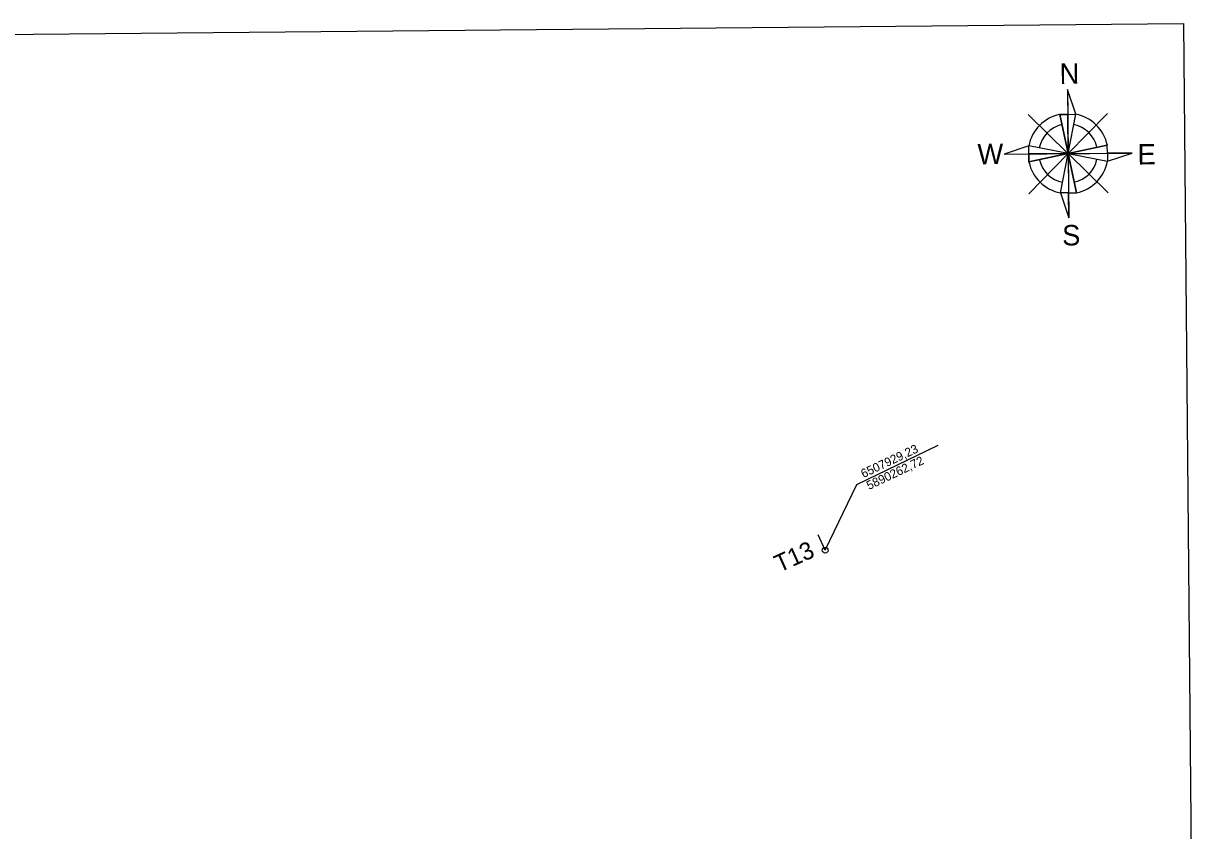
# Model space of a CAD drawing. Extents: x 6505045 to 6511721, y 5887996 to 5893535.
# Drawn here: x 6507860.2 to 6507961.4, y 5890238.6 to 5890308.1 of the extents above; entities that cross this region are included whole.
import ezdxf

# ---------------------------------------------------------------- set-up
doc = ezdxf.new("R2010")
doc.units = 0
for name, color, linetype in [('P_2 tablice LCD', 7, 'Continuous'), ('P_lokalizacja slupka', 7, 'Continuous'), ('P_opisy', 7, 'Continuous'), ('P_tabela', 7, 'Continuous'), ('P_wsporzedne', 7, 'Continuous'), ('P_znak północy', 7, 'Continuous')]:
    doc.layers.add(name, color=color, linetype=linetype)

msp = doc.modelspace()

# ---------------------------------------------------------------- linework, layer by layer
at = {"layer": 'P_2 tablice LCD'}
msp.add_line((6507929.23, 5890262.72), (6507928.62, 5890264.04), dxfattribs=at)
at = {"layer": 'P_lokalizacja slupka'}
msp.add_circle((6507929.23, 5890262.72), 0.25, dxfattribs=at)
at = {"layer": 'P_tabela'}
for p, q in [((6507759.07, 5890306.18), (6507960.06, 5890308.06)), ((6507759.07, 5890306.18), (6507960.06, 5890308.06)), ((6507759.07, 5890306.18), (6507960.06, 5890308.06)), ((6507960.06, 5890308.06), (6507961.36, 5890168.61)), ((6507960.06, 5890308.06), (6507961.36, 5890168.61)), ((6507960.06, 5890308.06), (6507961.36, 5890168.61))]:
    msp.add_line(p, q, dxfattribs=at)
at = {"layer": 'P_wsporzedne'}
for p, q in [((6507931.95, 5890268.37), (6507938.94, 5890271.76)), ((6507929.23, 5890262.72), (6507931.95, 5890268.37))]:
    msp.add_line(p, q, dxfattribs=at)
at = {"layer": 'P_znak północy'}
for p, q in [((6507950.09, 5890302.38), (6507950.19, 5890291.34)), ((6507950.09, 5890302.38), (6507950.19, 5890291.34)), ((6507950.09, 5890302.38), (6507950.19, 5890291.34)), ((6507950.09, 5890302.38), (6507950.19, 5890291.34)), ((6507950.09, 5890302.38), (6507950.19, 5890291.34)), ((6507950.09, 5890302.38), (6507950.19, 5890291.34)), ((6507950.09, 5890302.38), (6507950.19, 5890291.34)), ((6507950.09, 5890302.38), (6507950.19, 5890291.34)), ((6507950.12, 5890296.86), (6507946.69, 5890300.24)), ((6507950.12, 5890296.86), (6507946.69, 5890300.24)), ((6507950.12, 5890296.86), (6507946.69, 5890300.24)), ((6507950.12, 5890296.86), (6507946.69, 5890300.24)), ((6507950.12, 5890296.86), (6507946.69, 5890300.24)), ((6507950.12, 5890296.86), (6507946.69, 5890300.24)), ((6507950.12, 5890296.86), (6507946.69, 5890300.24)), ((6507950.12, 5890296.86), (6507946.69, 5890300.24)), ((6507949.42, 5890300.23), (6507950.11, 5890300.24)), ((6507949.42, 5890300.23), (6507950.11, 5890300.24)), ((6507949.42, 5890300.23), (6507950.11, 5890300.24)), ((6507949.42, 5890300.23), (6507950.11, 5890300.24)), ((6507949.42, 5890300.23), (6507950.11, 5890300.24)), ((6507949.42, 5890300.23), (6507950.11, 5890300.24)), ((6507949.42, 5890300.23), (6507950.11, 5890300.24)), ((6507949.42, 5890300.23), (6507950.11, 5890300.24)), ((6507950.14, 5890296.86), (6507949.42, 5890300.23)), ((6507950.14, 5890296.86), (6507949.42, 5890300.23)), ((6507950.14, 5890296.86), (6507949.42, 5890300.23)), ((6507950.14, 5890296.86), (6507949.42, 5890300.23)), ((6507950.14, 5890296.86), (6507949.42, 5890300.23)), ((6507950.14, 5890296.86), (6507949.42, 5890300.23)), ((6507950.14, 5890296.86), (6507949.42, 5890300.23)), ((6507950.14, 5890296.86), (6507949.42, 5890300.23)), ((6507950.11, 5890300.24), (6507950.8, 5890300.25)), ((6507950.11, 5890300.24), (6507950.8, 5890300.25)), ((6507950.11, 5890300.24), (6507950.8, 5890300.25)), ((6507950.11, 5890300.24), (6507950.8, 5890300.25)), ((6507950.11, 5890300.24), (6507950.8, 5890300.25)), ((6507950.11, 5890300.24), (6507950.8, 5890300.25)), ((6507950.11, 5890300.24), (6507950.8, 5890300.25)), ((6507950.11, 5890300.24), (6507950.8, 5890300.25)), ((6507950.14, 5890296.88), (6507953.52, 5890300.31)), ((6507950.14, 5890296.88), (6507953.52, 5890300.31)), ((6507950.14, 5890296.88), (6507953.52, 5890300.31)), ((6507950.14, 5890296.88), (6507953.52, 5890300.31)), ((6507950.14, 5890296.88), (6507953.52, 5890300.31)), ((6507950.14, 5890296.88), (6507953.52, 5890300.31)), ((6507950.14, 5890296.88), (6507953.52, 5890300.31)), ((6507950.14, 5890296.88), (6507953.52, 5890300.31)), ((6507950.14, 5890296.86), (6507950.8, 5890300.25)), ((6507950.14, 5890296.86), (6507950.8, 5890300.25)), ((6507950.14, 5890296.86), (6507950.8, 5890300.25)), ((6507950.14, 5890296.86), (6507950.8, 5890300.25)), ((6507950.14, 5890296.86), (6507950.8, 5890300.25)), ((6507950.14, 5890296.86), (6507950.8, 5890300.25)), ((6507950.14, 5890296.86), (6507950.8, 5890300.25)), ((6507950.14, 5890296.86), (6507950.8, 5890300.25)), ((6507944.62, 5890296.81), (6507955.66, 5890296.91)), ((6507944.62, 5890296.81), (6507955.66, 5890296.91)), ((6507944.62, 5890296.81), (6507955.66, 5890296.91)), ((6507944.62, 5890296.81), (6507955.66, 5890296.91)), ((6507944.62, 5890296.81), (6507955.66, 5890296.91)), ((6507944.62, 5890296.81), (6507955.66, 5890296.91)), ((6507944.62, 5890296.81), (6507955.66, 5890296.91)), ((6507944.62, 5890296.81), (6507955.66, 5890296.91)), ((6507950.14, 5890296.86), (6507946.75, 5890297.52)), ((6507950.14, 5890296.86), (6507946.75, 5890297.52)), ((6507950.14, 5890296.86), (6507946.75, 5890297.52)), ((6507950.14, 5890296.86), (6507946.75, 5890297.52)), ((6507950.14, 5890296.86), (6507946.75, 5890297.52)), ((6507950.14, 5890296.86), (6507946.75, 5890297.52)), ((6507950.14, 5890296.86), (6507946.75, 5890297.52)), ((6507950.14, 5890296.86), (6507946.75, 5890297.52)), ((6507950.14, 5890296.86), (6507953.51, 5890297.58)), ((6507950.14, 5890296.86), (6507953.51, 5890297.58)), ((6507950.14, 5890296.86), (6507953.51, 5890297.58)), ((6507950.14, 5890296.86), (6507953.51, 5890297.58)), ((6507950.14, 5890296.86), (6507953.51, 5890297.58)), ((6507950.14, 5890296.86), (6507953.51, 5890297.58)), ((6507950.14, 5890296.86), (6507953.51, 5890297.58)), ((6507950.14, 5890296.86), (6507953.51, 5890297.58)), ((6507950.14, 5890296.88), (6507946.75, 5890293.41)), ((6507950.14, 5890296.88), (6507946.75, 5890293.41)), ((6507950.14, 5890296.88), (6507946.75, 5890293.41)), ((6507950.14, 5890296.88), (6507946.75, 5890293.41)), ((6507950.14, 5890296.88), (6507946.75, 5890293.41)), ((6507950.14, 5890296.88), (6507946.75, 5890293.41)), ((6507950.14, 5890296.88), (6507946.75, 5890293.41)), ((6507950.14, 5890296.88), (6507946.75, 5890293.41)), ((6507946.76, 5890296.83), (6507950.12, 5890296.86)), ((6507946.76, 5890296.83), (6507950.12, 5890296.86)), ((6507946.76, 5890296.83), (6507950.12, 5890296.86)), ((6507946.76, 5890296.83), (6507950.12, 5890296.86)), ((6507946.76, 5890296.83), (6507950.12, 5890296.86)), ((6507946.76, 5890296.83), (6507950.12, 5890296.86)), ((6507946.76, 5890296.83), (6507950.12, 5890296.86)), ((6507946.76, 5890296.83), (6507950.12, 5890296.86)), ((6507946.77, 5890296.14), (6507946.76, 5890296.83)), ((6507946.77, 5890296.14), (6507946.76, 5890296.83)), ((6507946.77, 5890296.14), (6507946.76, 5890296.83)), ((6507946.77, 5890296.14), (6507946.76, 5890296.83)), ((6507946.77, 5890296.14), (6507946.76, 5890296.83)), ((6507946.77, 5890296.14), (6507946.76, 5890296.83)), ((6507946.77, 5890296.14), (6507946.76, 5890296.83)), ((6507946.77, 5890296.14), (6507946.76, 5890296.83)), ((6507946.77, 5890296.14), (6507950.14, 5890296.86)), ((6507950.12, 5890296.86), (6507946.77, 5890296.14)), ((6507946.77, 5890296.14), (6507950.14, 5890296.86)), ((6507950.12, 5890296.86), (6507946.77, 5890296.14)), ((6507946.77, 5890296.14), (6507950.14, 5890296.86)), ((6507950.12, 5890296.86), (6507946.77, 5890296.14)), ((6507946.77, 5890296.14), (6507950.14, 5890296.86)), ((6507950.12, 5890296.86), (6507946.77, 5890296.14)), ((6507946.77, 5890296.14), (6507950.14, 5890296.86)), ((6507950.12, 5890296.86), (6507946.77, 5890296.14)), ((6507946.77, 5890296.14), (6507950.14, 5890296.86)), ((6507950.12, 5890296.86), (6507946.77, 5890296.14)), ((6507946.77, 5890296.14), (6507950.14, 5890296.86)), ((6507950.12, 5890296.86), (6507946.77, 5890296.14)), ((6507946.77, 5890296.14), (6507950.14, 5890296.86)), ((6507950.12, 5890296.86), (6507946.77, 5890296.14)), ((6507949.48, 5890293.48), (6507950.14, 5890296.86)), ((6507949.48, 5890293.48), (6507950.14, 5890296.86)), ((6507949.48, 5890293.48), (6507950.14, 5890296.86)), ((6507949.48, 5890293.48), (6507950.14, 5890296.86)), ((6507949.48, 5890293.48), (6507950.14, 5890296.86)), ((6507949.48, 5890293.48), (6507950.14, 5890296.86)), ((6507949.48, 5890293.48), (6507950.14, 5890296.86)), ((6507949.48, 5890293.48), (6507950.14, 5890296.86)), ((6507950.14, 5890296.88), (6507953.58, 5890293.48)), ((6507950.14, 5890296.88), (6507953.58, 5890293.48)), ((6507950.14, 5890296.88), (6507953.58, 5890293.48)), ((6507950.14, 5890296.88), (6507953.58, 5890293.48)), ((6507950.14, 5890296.88), (6507953.58, 5890293.48)), ((6507950.14, 5890296.88), (6507953.58, 5890293.48)), ((6507950.14, 5890296.88), (6507953.58, 5890293.48)), ((6507950.14, 5890296.88), (6507953.58, 5890293.48)), ((6507950.14, 5890296.86), (6507953.52, 5890296.2)), ((6507950.14, 5890296.86), (6507950.86, 5890293.49)), ((6507950.14, 5890296.86), (6507953.52, 5890296.2)), ((6507950.14, 5890296.86), (6507950.86, 5890293.49)), ((6507950.14, 5890296.86), (6507953.52, 5890296.2)), ((6507950.14, 5890296.86), (6507950.86, 5890293.49)), ((6507950.14, 5890296.86), (6507953.52, 5890296.2)), ((6507950.14, 5890296.86), (6507950.86, 5890293.49)), ((6507950.14, 5890296.86), (6507953.52, 5890296.2)), ((6507950.14, 5890296.86), (6507950.86, 5890293.49)), ((6507950.14, 5890296.86), (6507953.52, 5890296.2)), ((6507950.14, 5890296.86), (6507950.86, 5890293.49)), ((6507950.14, 5890296.86), (6507953.52, 5890296.2)), ((6507950.14, 5890296.86), (6507950.86, 5890293.49)), ((6507950.14, 5890296.86), (6507953.52, 5890296.2)), ((6507950.14, 5890296.86), (6507950.86, 5890293.49))]:
    msp.add_line(p, q, dxfattribs=at)
for points in [[(6507950.09, 5890302.38), (6507950.11, 5890300.24), (6507950.11, 5890300.24), (6507950.8, 5890300.25), (6507950.09, 5890302.38)], [(6507950.09, 5890302.38), (6507950.11, 5890300.24), (6507950.11, 5890300.24), (6507950.8, 5890300.25), (6507950.09, 5890302.38)], [(6507950.09, 5890302.38), (6507950.11, 5890300.24), (6507950.11, 5890300.24), (6507950.8, 5890300.25), (6507950.09, 5890302.38)], [(6507950.09, 5890302.38), (6507950.11, 5890300.24), (6507950.11, 5890300.24), (6507950.8, 5890300.25), (6507950.09, 5890302.38)], [(6507950.09, 5890302.38), (6507950.11, 5890300.24), (6507950.11, 5890300.24), (6507950.8, 5890300.25), (6507950.09, 5890302.38)], [(6507950.09, 5890302.38), (6507950.11, 5890300.24), (6507950.11, 5890300.24), (6507950.8, 5890300.25), (6507950.09, 5890302.38)], [(6507950.09, 5890302.38), (6507950.11, 5890300.24), (6507950.11, 5890300.24), (6507950.8, 5890300.25), (6507950.09, 5890302.38)], [(6507950.09, 5890302.38), (6507950.11, 5890300.24), (6507950.11, 5890300.24), (6507950.8, 5890300.25), (6507950.09, 5890302.38)], [(6507950.14, 5890296.88), (6507950.11, 5890300.24), (6507949.42, 5890300.23), (6507950.14, 5890296.86), (6507950.14, 5890296.88)], [(6507950.14, 5890296.88), (6507950.11, 5890300.24), (6507949.42, 5890300.23), (6507950.14, 5890296.86), (6507950.14, 5890296.88)], [(6507950.14, 5890296.88), (6507950.11, 5890300.24), (6507949.42, 5890300.23), (6507950.14, 5890296.86), (6507950.14, 5890296.88)], [(6507950.14, 5890296.88), (6507950.11, 5890300.24), (6507949.42, 5890300.23), (6507950.14, 5890296.86), (6507950.14, 5890296.88)], [(6507950.14, 5890296.88), (6507950.11, 5890300.24), (6507949.42, 5890300.23), (6507950.14, 5890296.86), (6507950.14, 5890296.88)], [(6507950.14, 5890296.88), (6507950.11, 5890300.24), (6507949.42, 5890300.23), (6507950.14, 5890296.86), (6507950.14, 5890296.88)], [(6507950.14, 5890296.88), (6507950.11, 5890300.24), (6507949.42, 5890300.23), (6507950.14, 5890296.86), (6507950.14, 5890296.88)], [(6507950.14, 5890296.88), (6507950.11, 5890300.24), (6507949.42, 5890300.23), (6507950.14, 5890296.86), (6507950.14, 5890296.88)], [(6507946.76, 5890296.83), (6507946.75, 5890297.52), (6507944.62, 5890296.81), (6507946.76, 5890296.83)], [(6507946.76, 5890296.83), (6507946.75, 5890297.52), (6507944.62, 5890296.81), (6507946.76, 5890296.83)], [(6507946.76, 5890296.83), (6507946.75, 5890297.52), (6507944.62, 5890296.81), (6507946.76, 5890296.83)], [(6507946.76, 5890296.83), (6507946.75, 5890297.52), (6507944.62, 5890296.81), (6507946.76, 5890296.83)], [(6507946.76, 5890296.83), (6507946.75, 5890297.52), (6507944.62, 5890296.81), (6507946.76, 5890296.83)], [(6507946.76, 5890296.83), (6507946.75, 5890297.52), (6507944.62, 5890296.81), (6507946.76, 5890296.83)], [(6507946.76, 5890296.83), (6507946.75, 5890297.52), (6507944.62, 5890296.81), (6507946.76, 5890296.83)], [(6507946.76, 5890296.83), (6507946.75, 5890297.52), (6507944.62, 5890296.81), (6507946.76, 5890296.83)], [(6507950.14, 5890296.86), (6507950.14, 5890296.86), (6507950.15, 5890296.86), (6507953.52, 5890296.89), (6507953.51, 5890297.58), (6507950.14, 5890296.86)], [(6507950.14, 5890296.86), (6507950.14, 5890296.86), (6507950.15, 5890296.86), (6507953.52, 5890296.89), (6507953.51, 5890297.58), (6507950.14, 5890296.86)], [(6507950.14, 5890296.86), (6507950.14, 5890296.86), (6507950.15, 5890296.86), (6507953.52, 5890296.89), (6507953.51, 5890297.58), (6507950.14, 5890296.86)], [(6507950.14, 5890296.86), (6507950.14, 5890296.86), (6507950.15, 5890296.86), (6507953.52, 5890296.89), (6507953.51, 5890297.58), (6507950.14, 5890296.86)], [(6507950.14, 5890296.86), (6507950.14, 5890296.86), (6507950.15, 5890296.86), (6507953.52, 5890296.89), (6507953.51, 5890297.58), (6507950.14, 5890296.86)], [(6507950.14, 5890296.86), (6507950.14, 5890296.86), (6507950.15, 5890296.86), (6507953.52, 5890296.89), (6507953.51, 5890297.58), (6507950.14, 5890296.86)], [(6507950.14, 5890296.86), (6507950.14, 5890296.86), (6507950.15, 5890296.86), (6507953.52, 5890296.89), (6507953.51, 5890297.58), (6507950.14, 5890296.86)], [(6507950.14, 5890296.86), (6507950.14, 5890296.86), (6507950.15, 5890296.86), (6507953.52, 5890296.89), (6507953.51, 5890297.58), (6507950.14, 5890296.86)], [(6507955.66, 5890296.91), (6507953.52, 5890296.89), (6507953.52, 5890296.2), (6507955.66, 5890296.91)], [(6507955.66, 5890296.91), (6507953.52, 5890296.89), (6507953.52, 5890296.2), (6507955.66, 5890296.91)], [(6507955.66, 5890296.91), (6507953.52, 5890296.89), (6507953.52, 5890296.2), (6507955.66, 5890296.91)], [(6507955.66, 5890296.91), (6507953.52, 5890296.89), (6507953.52, 5890296.2), (6507955.66, 5890296.91)], [(6507955.66, 5890296.91), (6507953.52, 5890296.89), (6507953.52, 5890296.2), (6507955.66, 5890296.91)], [(6507955.66, 5890296.91), (6507953.52, 5890296.89), (6507953.52, 5890296.2), (6507955.66, 5890296.91)], [(6507955.66, 5890296.91), (6507953.52, 5890296.89), (6507953.52, 5890296.2), (6507955.66, 5890296.91)], [(6507955.66, 5890296.91), (6507953.52, 5890296.89), (6507953.52, 5890296.2), (6507955.66, 5890296.91)], [(6507950.12, 5890296.86), (6507946.76, 5890296.83), (6507946.77, 5890296.14), (6507950.12, 5890296.86)], [(6507950.12, 5890296.86), (6507946.76, 5890296.83), (6507946.77, 5890296.14), (6507950.12, 5890296.86)], [(6507950.12, 5890296.86), (6507946.76, 5890296.83), (6507946.77, 5890296.14), (6507950.12, 5890296.86)], [(6507950.12, 5890296.86), (6507946.76, 5890296.83), (6507946.77, 5890296.14), (6507950.12, 5890296.86)], [(6507950.12, 5890296.86), (6507946.76, 5890296.83), (6507946.77, 5890296.14), (6507950.12, 5890296.86)], [(6507950.12, 5890296.86), (6507946.76, 5890296.83), (6507946.77, 5890296.14), (6507950.12, 5890296.86)], [(6507950.12, 5890296.86), (6507946.76, 5890296.83), (6507946.77, 5890296.14), (6507950.12, 5890296.86)], [(6507950.12, 5890296.86), (6507946.76, 5890296.83), (6507946.77, 5890296.14), (6507950.12, 5890296.86)], [(6507950.17, 5890293.48), (6507950.86, 5890293.49), (6507950.14, 5890296.85), (6507950.17, 5890293.48)], [(6507950.17, 5890293.48), (6507950.86, 5890293.49), (6507950.14, 5890296.85), (6507950.17, 5890293.48)], [(6507950.17, 5890293.48), (6507950.86, 5890293.49), (6507950.14, 5890296.85), (6507950.17, 5890293.48)], [(6507950.17, 5890293.48), (6507950.86, 5890293.49), (6507950.14, 5890296.85), (6507950.17, 5890293.48)], [(6507950.17, 5890293.48), (6507950.86, 5890293.49), (6507950.14, 5890296.85), (6507950.17, 5890293.48)], [(6507950.17, 5890293.48), (6507950.86, 5890293.49), (6507950.14, 5890296.85), (6507950.17, 5890293.48)], [(6507950.17, 5890293.48), (6507950.86, 5890293.49), (6507950.14, 5890296.85), (6507950.17, 5890293.48)], [(6507950.17, 5890293.48), (6507950.86, 5890293.49), (6507950.14, 5890296.85), (6507950.17, 5890293.48)], [(6507950.17, 5890293.48), (6507949.48, 5890293.48), (6507950.19, 5890291.34), (6507950.17, 5890293.48)], [(6507950.17, 5890293.48), (6507949.48, 5890293.48), (6507950.19, 5890291.34), (6507950.17, 5890293.48)], [(6507950.17, 5890293.48), (6507949.48, 5890293.48), (6507950.19, 5890291.34), (6507950.17, 5890293.48)], [(6507950.17, 5890293.48), (6507949.48, 5890293.48), (6507950.19, 5890291.34), (6507950.17, 5890293.48)], [(6507950.17, 5890293.48), (6507949.48, 5890293.48), (6507950.19, 5890291.34), (6507950.17, 5890293.48)], [(6507950.17, 5890293.48), (6507949.48, 5890293.48), (6507950.19, 5890291.34), (6507950.17, 5890293.48)], [(6507950.17, 5890293.48), (6507949.48, 5890293.48), (6507950.19, 5890291.34), (6507950.17, 5890293.48)], [(6507950.17, 5890293.48), (6507949.48, 5890293.48), (6507950.19, 5890291.34), (6507950.17, 5890293.48)]]:
    msp.add_lwpolyline(points, dxfattribs=at)
for centre, radius, start, end in [((6507950.13, 5890296.86), 3.45, 102.0474, 168.9738), ((6507950.13, 5890296.86), 3.45, 102.0474, 168.9738), ((6507950.13, 5890296.86), 3.45, 102.0474, 168.9738), ((6507950.13, 5890296.86), 3.45, 102.0474, 168.9738), ((6507950.13, 5890296.86), 3.45, 102.0474, 168.9738), ((6507950.13, 5890296.86), 3.45, 102.0474, 168.9738), ((6507950.13, 5890296.86), 3.45, 102.0474, 168.9738), ((6507950.13, 5890296.86), 3.45, 102.0474, 168.9738), ((6507950.14, 5890296.86), 3.45, 12.0554, 79.0163), ((6507950.14, 5890296.86), 3.45, 12.0554, 79.0163), ((6507950.14, 5890296.86), 3.45, 12.0554, 79.0163), ((6507950.14, 5890296.86), 3.45, 12.0554, 79.0163), ((6507950.14, 5890296.86), 3.45, 12.0554, 79.0163), ((6507950.14, 5890296.86), 3.45, 12.0554, 79.0163), ((6507950.14, 5890296.86), 3.45, 12.0554, 79.0163), ((6507950.14, 5890296.86), 3.45, 12.0554, 79.0163), ((6507950.14, 5890296.88), 2.53, 102.1671, 169.2958), ((6507950.14, 5890296.88), 2.53, 102.1671, 169.2958), ((6507950.14, 5890296.88), 2.53, 102.1671, 169.2958), ((6507950.14, 5890296.88), 2.53, 102.1671, 169.2958), ((6507950.14, 5890296.88), 2.53, 102.1671, 169.2958), ((6507950.14, 5890296.88), 2.53, 102.1671, 169.2958), ((6507950.14, 5890296.88), 2.53, 102.1671, 169.2958), ((6507950.14, 5890296.88), 2.53, 102.1671, 169.2958), ((6507950.14, 5890296.88), 2.53, 11.7816, 78.9353), ((6507950.14, 5890296.88), 2.53, 11.7816, 78.9353), ((6507950.14, 5890296.88), 2.53, 11.7816, 78.9353), ((6507950.14, 5890296.88), 2.53, 11.7816, 78.9353), ((6507950.14, 5890296.88), 2.53, 11.7816, 78.9353), ((6507950.14, 5890296.88), 2.53, 11.7816, 78.9353), ((6507950.14, 5890296.88), 2.53, 11.7816, 78.9353), ((6507950.14, 5890296.88), 2.53, 11.7816, 78.9353), ((6507950.14, 5890296.86), 3.45, 192.0538, 259.0158), ((6507950.14, 5890296.86), 3.45, 192.0538, 259.0158), ((6507950.14, 5890296.86), 3.45, 192.0538, 259.0158), ((6507950.14, 5890296.86), 3.45, 192.0538, 259.0158), ((6507950.14, 5890296.86), 3.45, 192.0538, 259.0158), ((6507950.14, 5890296.86), 3.45, 192.0538, 259.0158), ((6507950.14, 5890296.86), 3.45, 192.0538, 259.0158), ((6507950.14, 5890296.86), 3.45, 192.0538, 259.0158), ((6507950.14, 5890296.88), 2.53, 192.3917, 259.0318), ((6507950.14, 5890296.88), 2.53, 192.3917, 259.0318), ((6507950.14, 5890296.88), 2.53, 192.3917, 259.0318), ((6507950.14, 5890296.88), 2.53, 192.3917, 259.0318), ((6507950.14, 5890296.88), 2.53, 192.3917, 259.0318), ((6507950.14, 5890296.88), 2.53, 192.3917, 259.0318), ((6507950.14, 5890296.88), 2.53, 192.3917, 259.0318), ((6507950.14, 5890296.88), 2.53, 192.3917, 259.0318), ((6507950.14, 5890296.88), 2.53, 282.0081, 348.6723), ((6507950.14, 5890296.88), 2.53, 282.0081, 348.6723), ((6507950.14, 5890296.88), 2.53, 282.0081, 348.6723), ((6507950.14, 5890296.88), 2.53, 282.0081, 348.6723), ((6507950.14, 5890296.88), 2.53, 282.0081, 348.6723), ((6507950.14, 5890296.88), 2.53, 282.0081, 348.6723), ((6507950.14, 5890296.88), 2.53, 282.0081, 348.6723), ((6507950.14, 5890296.88), 2.53, 282.0081, 348.6723), ((6507950.14, 5890296.86), 3.45, 282.0538, 349.0163), ((6507950.14, 5890296.86), 3.45, 282.0538, 349.0163), ((6507950.14, 5890296.86), 3.45, 282.0538, 349.0163), ((6507950.14, 5890296.86), 3.45, 282.0538, 349.0163), ((6507950.14, 5890296.86), 3.45, 282.0538, 349.0163), ((6507950.14, 5890296.86), 3.45, 282.0538, 349.0163), ((6507950.14, 5890296.86), 3.45, 282.0538, 349.0163), ((6507950.14, 5890296.86), 3.45, 282.0538, 349.0163)]:
    msp.add_arc(centre, radius, start, end, dxfattribs=at)

# ---------------------------------------------------------------- texts
at = {"layer": 'P_opisy'}
msp.add_text('T13', height=1.501, rotation=24.2052, dxfattribs=at).set_placement((6507925.28, 5890260.78))
at = {"layer": 'P_wsporzedne'}
for s, p in [('6507929,23', (6507932.52, 5890268.92)), ('5890262,72', (6507933, 5890267.9))]:
    msp.add_text(s, height=0.751, rotation=25.405, dxfattribs=at).set_placement(p)
at = {"layer": 'P_znak północy'}
for s, p in [('N', (6507949.41, 5890302.86)), ('N', (6507949.41, 5890302.86)), ('N', (6507949.41, 5890302.86)), ('N', (6507949.41, 5890302.86)), ('N', (6507949.41, 5890302.86)), ('N', (6507949.41, 5890302.86)), ('N', (6507949.41, 5890302.86)), ('N', (6507949.41, 5890302.86)), ('W', (6507942.34, 5890295.94)), ('W', (6507942.34, 5890295.94)), ('W', (6507942.34, 5890295.94)), ('W', (6507942.34, 5890295.94)), ('W', (6507942.34, 5890295.94)), ('W', (6507942.34, 5890295.94)), ('W', (6507942.34, 5890295.94)), ('W', (6507942.34, 5890295.94)), ('E', (6507956.12, 5890295.92)), ('E', (6507956.12, 5890295.92)), ('E', (6507956.12, 5890295.92)), ('E', (6507956.12, 5890295.92)), ('E', (6507956.12, 5890295.92)), ('E', (6507956.12, 5890295.92)), ('E', (6507956.12, 5890295.92)), ('E', (6507956.12, 5890295.92)), ('S', (6507949.63, 5890288.95)), ('S', (6507949.63, 5890288.95)), ('S', (6507949.63, 5890288.95)), ('S', (6507949.63, 5890288.95)), ('S', (6507949.63, 5890288.95)), ('S', (6507949.63, 5890288.95)), ('S', (6507949.63, 5890288.95)), ('S', (6507949.63, 5890288.95))]:
    msp.add_text(s, height=1.76, rotation=0.535, dxfattribs=at).set_placement(p)

doc.saveas('drawing.dxf')
